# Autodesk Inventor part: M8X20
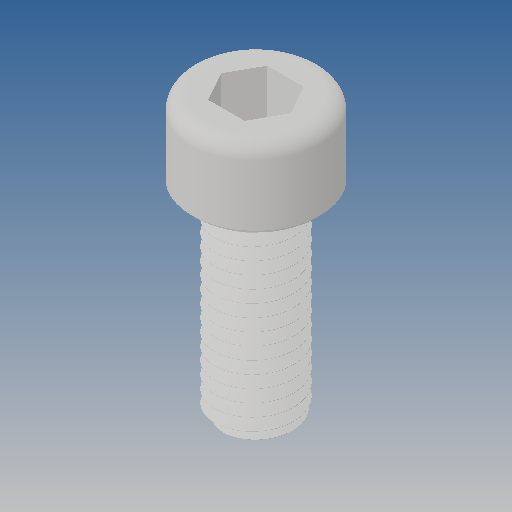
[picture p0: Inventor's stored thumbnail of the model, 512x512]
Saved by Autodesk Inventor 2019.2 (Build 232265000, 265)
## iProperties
Created: 2010-02
Part Number: M8X20
Material: Ogólny
Document SubType Name: Modeling
Designer: CADENGINEERING4
Density: 1 g/cm^3
Appearance: Domyślna
Author: CADENGINEERING4
Revision Number: 1LAST_VERSION
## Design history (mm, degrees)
feature "Baza1"
node "Bryła1"
